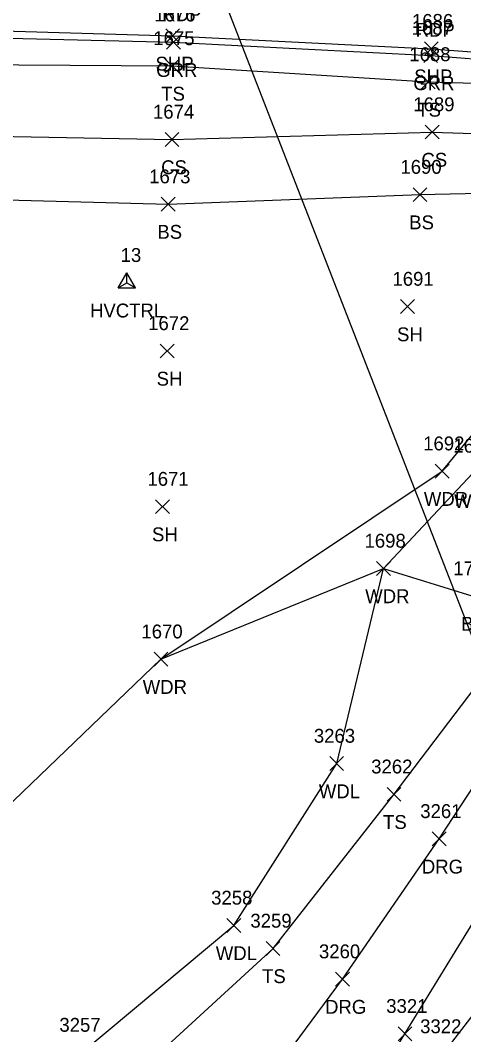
# Model space of a CAD drawing. Extents: x 49137 to 50946, y 9590 to 10709.
# Drawn here: x 50328.9 to 50392.8, y 9908.7 to 10054.9 of the extents above; entities that cross this region are included whole.
import ezdxf

# ---------------------------------------------------------------- set-up
doc = ezdxf.new("R2010")
doc.units = 0
for name, color, linetype in [('C_A', 7, 'Continuous'), ('C_I', 7, 'Continuous'), ('CPSM', 7, 'Continuous'), ('DCP', 7, 'Continuous'), ('L_A', 7, 'Continuous'), ('L_I', 7, 'Continuous'), ('L_TIC', 7, 'Continuous'), ('LAWA', 7, 'Continuous'), ('LELB', 7, 'Continuous'), ('LSOGP', 7, 'Continuous'), ('P_A', 7, 'Continuous'), ('P_I', 7, 'Continuous'), ('P_TIC', 7, 'Continuous'), ('PSP', 7, 'Continuous'), ('R_A', 7, 'Continuous'), ('R_I', 7, 'Continuous'), ('R_TIC', 7, 'Continuous'), ('RDG', 7, 'Continuous'), ('RGR', 7, 'Continuous')]:
    doc.layers.add(name, color=color, linetype=linetype)

msp = doc.modelspace()

# ---------------------------------------------------------------- linework, layer by layer
at = {"layer": 'CPSM'}
for p, q in [((50343.01, 10016.36), (50344.26, 10018.53)), ((50345.51, 10016.36), (50344.26, 10018.53)), ((50344.26, 10017.08), (50344.26, 10018.53)), ((50343.01, 10016.36), (50344.26, 10017.08)), ((50344.26, 10017.08), (50344.26, 10017.08)), ((50344.26, 10017.08), (50345.51, 10016.36)), ((50343.01, 10016.36), (50345.51, 10016.36))]:
    msp.add_line(p, q, dxfattribs=at)
at = {"layer": 'DCP'}
msp.add_lwpolyline([(49941.69, 9827.48), (50059.34, 9808.37), (50181.4, 9733.09), (50281.74, 9743.29), (50422.72, 9892.52), (50122.34, 10663.61), (50179.93, 10552.61), (50179.64, 10394.45), (50122.34, 10285.07), (50121.56, 10284.35)], dxfattribs=at)
at = {"layer": 'L_TIC'}
for points in [[(50349.81, 10047.34), (50351.81, 10049.34)], [(50351.81, 10047.34), (50349.81, 10049.34)], [(50386.74, 10045.03), (50388.74, 10047.03)], [(50388.74, 10045.03), (50386.74, 10047.03)], [(50349.77, 10036.74), (50351.77, 10038.74)], [(50351.77, 10036.74), (50349.77, 10038.74)], [(50387.31, 10037.81), (50389.31, 10039.81)], [(50389.31, 10037.81), (50387.31, 10039.81)], [(50385.55, 10028.79), (50387.55, 10030.79)], [(50387.55, 10028.79), (50385.55, 10030.79)], [(50349.22, 10027.42), (50351.22, 10029.42)], [(50351.22, 10027.42), (50349.22, 10029.42)], [(50383.75, 10012.65), (50385.75, 10014.65)], [(50385.75, 10012.65), (50383.75, 10014.65)], [(50349.07, 10006.25), (50351.07, 10008.25)], [(50351.07, 10006.25), (50349.07, 10008.25)], [(50388.74, 9988.92), (50390.74, 9990.92)], [(50390.74, 9988.92), (50388.74, 9990.92)], [(50348.41, 9983.81), (50350.41, 9985.81)], [(50350.41, 9983.81), (50348.41, 9985.81)], [(50380.28, 9974.89), (50382.28, 9976.89)], [(50382.28, 9974.89), (50380.28, 9976.89)], [(50348.18, 9961.81), (50350.18, 9963.81)], [(50350.18, 9961.81), (50348.18, 9963.81)], [(50373.53, 9946.77), (50375.53, 9948.77)], [(50375.53, 9946.77), (50373.53, 9948.77)], [(50381.8, 9942.34), (50383.8, 9944.34)], [(50383.8, 9942.34), (50381.8, 9944.34)], [(50358.68, 9923.43), (50360.68, 9925.43)], [(50360.68, 9923.43), (50358.68, 9925.43)], [(50364.35, 9920.11), (50366.35, 9922.11)], [(50366.35, 9920.11), (50364.35, 9922.11)]]:
    msp.add_lwpolyline(points, dxfattribs=at)
at = {"layer": 'LAWA'}
for points in [[(50319.22, 9934.09), (50349.18, 9962.81), (50389.74, 9989.92), (50402.83, 10005.7), (50406.6, 10004.03), (50394.1, 9989.59), (50381.28, 9975.89)], [(50374.53, 9947.77), (50381.28, 9975.89)], [(50269.38, 9910.32), (50295.29, 9895.71), (50319.1, 9895.53), (50337.78, 9906.1), (50359.68, 9924.43), (50374.53, 9947.77)]]:
    msp.add_lwpolyline(points, dxfattribs=at)
at = {"layer": 'LELB'}
for points in [[(50167.44, 10041.81), (50201.55, 10044.88), (50212.32, 10046.12), (50246.1, 10048.99), (50272.8, 10048.46), (50313.94, 10048.62), (50350.81, 10048.34), (50387.74, 10046.03), (50413.04, 10045.35), (50435.45, 10042.61), (50477, 10035.72), (50497.96, 10034.79)], [(50107.47, 10020.38), (50144.2, 10028.78), (50165.65, 10031.22), (50202.05, 10039.61), (50215.24, 10036.08), (50246.55, 10038.53), (50272.19, 10036.43), (50315.22, 10038.43), (50350.77, 10037.74), (50388.31, 10038.81), (50412.12, 10038.05), (50434.22, 10033.95), (50476.27, 10030.6), (50502.33, 10026.06), (50519.95, 10026.12), (50528.33, 10023.44), (50558.5, 10017.09), (50596.1, 10007.75), (50623.13, 10001.96)], [(50278.22, 10023.17), (50289.26, 10024.35), (50316.04, 10029.33), (50350.22, 10028.42), (50386.55, 10029.79), (50399.58, 10030.09)], [(50382.8, 9943.34), (50400.43, 9966.53)], [(50365.14, 9877.47), (50389.82, 9905.89), (50402.42, 9922.22), (50417.66, 9947.41), (50430.73, 9954.36)], [(50314.49, 9855.16), (50332.43, 9882.14), (50336.66, 9894.79), (50365.35, 9921.11), (50382.8, 9943.34)]]:
    msp.add_lwpolyline(points, dxfattribs=at)
at = {"layer": 'LSOGP'}
msp.add_lwpolyline([(50172.36, 9837.78), (50185.48, 9838.52), (50189.39, 9851.5), (50202.19, 9864.77), (50219.85, 9877.61), (50226.92, 9887.06), (50233.45, 9889.4), (50242.1, 9900.88), (50265.38, 9914.66), (50319.22, 9934.09), (50349.18, 9962.81), (50381.27, 9975.89), (50394.04, 9971.93), (50398.71, 9968.32), (50400.43, 9966.52), (50406.78, 9963.51), (50419.71, 9962.53), (50427.02, 9958.62), (50466.07, 9973.83), (50480.4, 9980.25), (50492.08, 9978.32), (50501.38, 9976.22)], dxfattribs=at)
at = {"layer": 'P_TIC'}
for points in [[(50349.86, 10051.67), (50351.86, 10053.67)], [(50351.86, 10051.67), (50349.86, 10053.67)], [(50387.17, 10049.83), (50389.17, 10051.83)], [(50389.17, 10049.83), (50387.17, 10051.83)]]:
    msp.add_lwpolyline(points, dxfattribs=at)
at = {"layer": 'PSP'}
msp.add_lwpolyline([(49745.77, 9936.94), (49791.02, 9949.79), (49838.6, 9962.98), (49884.65, 9976.31), (49920.32, 9986.67), (49952.97, 9996.21), (49993.49, 10007.72), (50041.55, 10020.44), (50079.02, 10029.05), (50103.84, 10034.11), (50138.34, 10040.53), (50167.13, 10044.8), (50204.38, 10048.62), (50245.47, 10052.53), (50273.99, 10052.71), (50313.27, 10053.81), (50350.86, 10052.67), (50388.17, 10050.83), (50414.17, 10048.89), (50435.24, 10046.38), (50477.89, 10041.39), (50498.49, 10037.53)], dxfattribs=at)
at = {"layer": 'R_TIC'}
for points in [[(50350, 10050.76), (50352, 10052.76)], [(50352, 10050.76), (50350, 10052.76)], [(50387.09, 10048.85), (50389.09, 10050.85)], [(50389.09, 10048.85), (50387.09, 10050.85)], [(50388.32, 9935.91), (50390.32, 9937.91)], [(50390.32, 9935.91), (50388.32, 9937.91)], [(50374.36, 9915.69), (50376.36, 9917.69)], [(50376.36, 9915.69), (50374.36, 9917.69)], [(50383.37, 9907.81), (50385.37, 9909.81)], [(50385.37, 9907.81), (50383.37, 9909.81)]]:
    msp.add_lwpolyline(points, dxfattribs=at)
at = {"layer": 'RDG'}
for points in [[(50389.32, 9936.91), (50406.78, 9963.51)], [(50261.11, 9892.73), (50266.99, 9900.96), (50287.76, 9883.23), (50308.32, 9860.48), (50314.49, 9855.16), (50323.34, 9846.19), (50341.84, 9871.41), (50375.36, 9916.69), (50389.32, 9936.91)], [(50335.39, 9819.52), (50333.76, 9830.34), (50344.19, 9849.34), (50365.14, 9877.47), (50384.37, 9908.81), (50396.05, 9927.82)]]:
    msp.add_lwpolyline(points, dxfattribs=at)
at = {"layer": 'RGR'}
msp.add_lwpolyline([(49745.96, 9935.74), (49791.34, 9948.66), (49838.49, 9962.28), (49885.39, 9975.73), (49920.7, 9985.37), (49953.18, 9995.29), (49993.74, 10006.79), (50040.75, 10019.43), (50079.3, 10027.88), (50102.09, 10032.68), (50138.52, 10039.64), (50167.15, 10043.61), (50204.31, 10047.75), (50245.69, 10050.91), (50273.98, 10052), (50313.38, 10052.67), (50351, 10051.76), (50388.09, 10049.85), (50414.02, 10047.85), (50436.27, 10045.35), (50477.66, 10040.11), (50498.48, 10036.57)], dxfattribs=at)

# ---------------------------------------------------------------- texts
at = {"layer": 'C_A'}
msp.add_text('HVCTRL', height=2, dxfattribs=at).set_placement((50338.95, 10012.08))
at = {"layer": 'C_I'}
msp.add_text('13', height=2, dxfattribs=at).set_placement((50343.36, 10020.08))
at = {"layer": 'L_A'}
for s, p in [('TS', (50349.22, 10043.34)), ('TS', (50386.15, 10041.03)), ('CS', (50386.75, 10033.81)), ('CS', (50349.21, 10032.74)), ('BS', (50384.99, 10024.79)), ('BS', (50348.66, 10023.42)), ('SH', (50383.23, 10008.65)), ('SH', (50348.56, 10002.25)), ('WDR', (50387.1, 9984.92)), ('WDR', (50391.46, 9984.59)), ('SH', (50347.89, 9979.81)), ('WDR', (50378.64, 9970.89)), ('BS', (50392.48, 9966.92)), ('WDR', (50346.55, 9957.81)), ('WDL', (50371.95, 9942.77)), ('TS', (50381.21, 9938.34)), ('WDL', (50357.09, 9919.43)), ('TS', (50363.76, 9916.11))]:
    msp.add_text(s, height=2, dxfattribs=at).set_placement(p)
at = {"layer": 'L_I'}
for s, p in [('1675', (50348.07, 10051.34)), ('1688', (50385, 10049.03)), ('1689', (50385.57, 10041.81)), ('1674', (50348.03, 10040.74)), ('1690', (50383.72, 10032.79)), ('1673', (50347.48, 10031.42)), ('1691', (50382.57, 10016.65)), ('1672', (50347.33, 10010.25)), ('1692', (50387, 9992.92)), ('1697', (50391.36, 9992.59)), ('1671', (50347.23, 9987.81)), ('1698', (50378.54, 9978.89)), ('1724', (50391.35, 9974.92)), ('1670', (50346.36, 9965.81)), ('3263', (50371.23, 9950.77)), ('3262', (50379.5, 9946.34)), ('3258', (50356.42, 9927.43)), ('3259', (50362.08, 9924.11)), ('3257', (50334.53, 9909.1)), ('3257', (50334.53, 9909.1)), ('3322', (50386.56, 9908.89))]:
    msp.add_text(s, height=2, dxfattribs=at).set_placement(p)
at = {"layer": 'P_A'}
for s, p in [('RDP', (50349.37, 10054.79)), ('RDP', (50385.91, 10052.55)), ('SHP', (50348.4, 10047.67)), ('SHP', (50385.71, 10045.83))]:
    msp.add_text(s, height=2, dxfattribs=at).set_placement(p)
at = {"layer": 'P_I'}
msp.add_text('1686', height=2, dxfattribs=at).set_placement((50385.38, 10053.83))
at = {"layer": 'R_A'}
for s, p in [('GRR', (50348.49, 10046.76)), ('GRR', (50385.57, 10044.85)), ('DRG', (50386.81, 9931.91)), ('DRG', (50372.85, 9911.69))]:
    msp.add_text(s, height=2, dxfattribs=at).set_placement(p)
at = {"layer": 'R_I'}
for s, p in [('1676', (50348.21, 10054.76)), ('1687', (50385.35, 10052.85)), ('3261', (50386.58, 9939.91)), ('3260', (50371.97, 9919.69)), ('3321', (50381.67, 9911.81))]:
    msp.add_text(s, height=2, dxfattribs=at).set_placement(p)

doc.saveas('drawing.dxf')
